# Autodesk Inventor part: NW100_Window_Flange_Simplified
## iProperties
Shininess: 64.0
Length Units: 11269
Angle Units: 11279
Time Units: 11290
Mass Units: 11283
Length Display Precision: 3
Angle Display Precision: 2
Compacted: True
Part Number: NW100_Window_Flange_Simplified
Document SubType Name: Modeling
Created: 2004-07
Designer: John Blackburn
Manufacturer: Standard
Standards Organization: Custom
Density: 0.0
Volumn: 0.0
Area: 0.0
PropertySet Name: Model Information
Control State: 0
Master: False
Checked Out: False
Author: John Blackburn
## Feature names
1. Extrusion1
